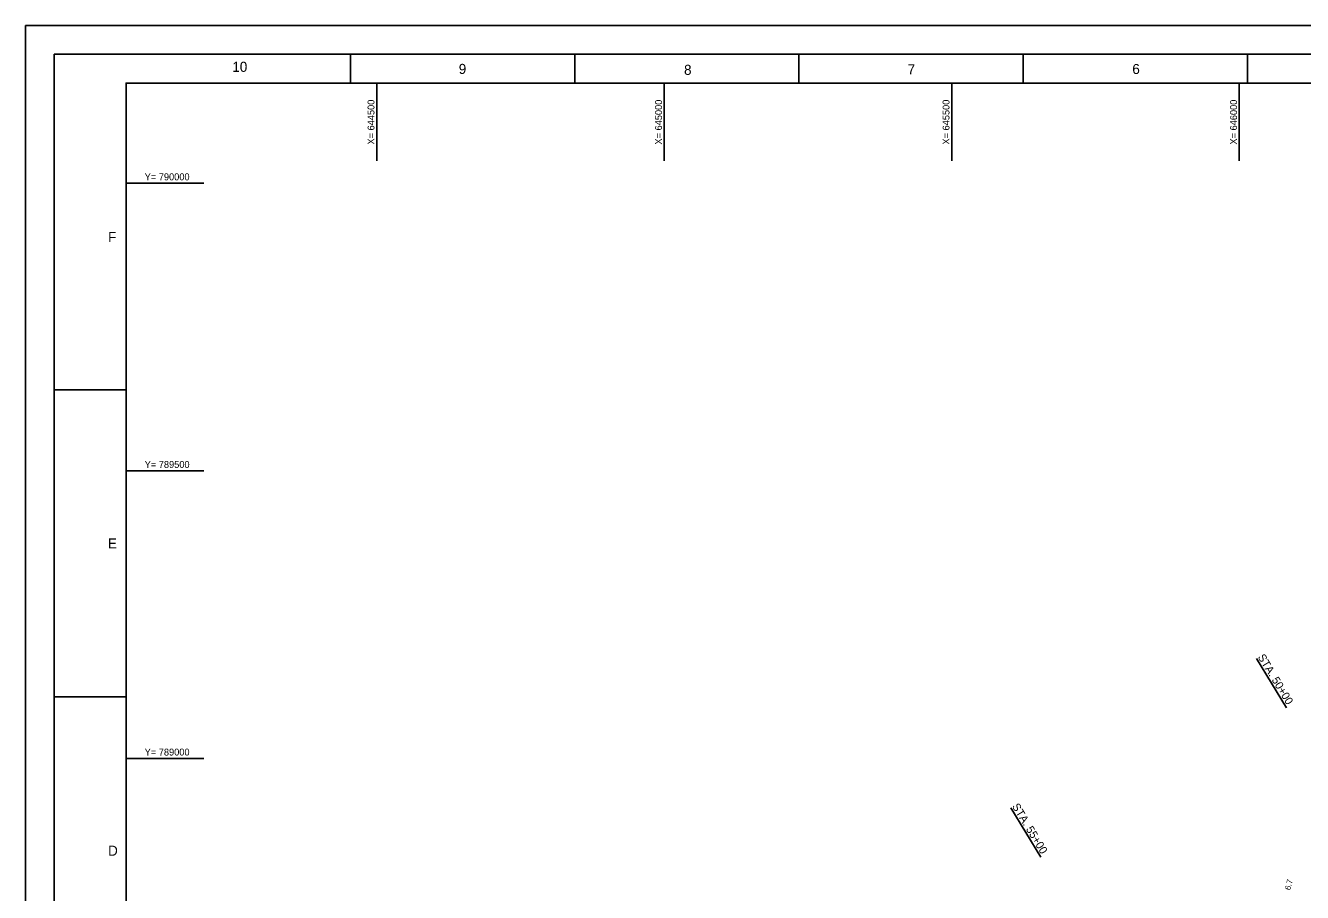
# Model space of a CAD drawing. Extents: x 643889 to 648289, y 786874 to 790274.
# Drawn here: x 643889 to 646110, y 788767 to 790274 of the extents above; entities that cross this region are included whole.
import ezdxf

# ---------------------------------------------------------------- set-up
doc = ezdxf.new("R2010")
doc.units = 0
for name, color, linetype in [('G-ANNO-NPLT', 7, 'Continuous'), ('G-ANNO-TTLB', 7, 'Continuous'), ('V-ALGN-TEXT', 7, 'Continuous'), ('V-TOPO-COOR-STAT', 7, 'Continuous'), ('V-TOPO-SOUN', 7, 'Continuous')]:
    doc.layers.add(name, color=color, linetype=linetype)

msp = doc.modelspace()

# ---------------------------------------------------------------- linework, layer by layer
at = {"layer": 'G-ANNO-NPLT'}
msp.add_lwpolyline([(643889.2, 790274), (648289.2, 790274), (648289.2, 786874), (643889.2, 786874)], close=True, dxfattribs=at)
msp.add_lwpolyline([(643889.2, 790224), (643889.2, 790274), (643939.2, 790274)], dxfattribs=at)
at = {"layer": 'G-ANNO-TTLB'}
for p, q in [((644454.2, 790224), (644454.2, 790174)), ((644844.2, 790224), (644844.2, 790174)), ((644844.2, 790224), (644844.2, 790174)), ((645234.2, 790224), (645234.2, 790174)), ((645624.2, 790224), (645624.2, 790174)), ((646014.2, 790224), (646014.2, 790174)), ((643939.2, 789640.5), (644064.2, 789640.5)), ((643939.2, 789107.2), (644064.2, 789107.2))]:
    msp.add_line(p, q, dxfattribs=at)
for points in [[(643939.2, 786924), (648239.2, 786924), (648239.2, 790224), (643939.2, 790224)], [(648189.2, 790174), (644064.2, 790174), (644064.2, 786974), (648189.2, 786974)]]:
    msp.add_lwpolyline(points, close=True, dxfattribs=at)
at = {"layer": 'V-ALGN-TEXT'}
for p, q in [((646030, 789173.4), (646081.9, 789088)), ((645602.7, 788913.9), (645654.6, 788828.4))]:
    msp.add_line(p, q, dxfattribs=at)
at = {"layer": 'V-TOPO-COOR-STAT'}
for p, q in [((644500, 790039), (644500, 790174)), ((645000, 790039), (645000, 790174)), ((645500, 790039), (645500, 790174)), ((646000, 790039), (646000, 790174)), ((644064.2, 790000), (644199.2, 790000)), ((644064.2, 789500), (644199.2, 789500)), ((644064.2, 789000), (644199.2, 789000))]:
    msp.add_line(p, q, dxfattribs=at)

# ---------------------------------------------------------------- texts
at = {"layer": 'G-ANNO-TTLB'}
for s, p in [('10', (644248.8, 790193.5)), ('9', (644642.6, 790189.9)), ('8', (645034.4, 790188.3)), ('7', (645423.1, 790189)), ('6', (645814, 790189.7)), ('F', (644032.8, 789897.6)), ('E', (644032.6, 789364.9)), ('D', (644032.8, 788830.8))]:
    msp.add_text(s, height=17.5, dxfattribs=at).set_placement(p)
at = {"layer": 'V-ALGN-TEXT'}
for s, p in [('STA. 50+00', (646031.5, 789176.3)), ('STA. 55+00', (645604.2, 788916.8))]:
    msp.add_text(s, height=13.92, rotation=301.2715, dxfattribs=at).set_placement(p)
at = {"layer": 'V-TOPO-COOR-STAT'}
for s, p in [('X= 644500', (644496, 790067.1)), ('X= 645000', (644996, 790067.1)), ('X= 645500', (645496, 790067.1)), ('X= 646000', (645996, 790067.1))]:
    msp.add_text(s, height=12, rotation=90, dxfattribs=at).set_placement(p)
for s, p in [('Y= 790000', (644096.4, 790005)), ('Y= 789500', (644096.4, 789505)), ('Y= 789000', (644096.4, 789005))]:
    msp.add_text(s, height=12, dxfattribs=at).set_placement(p)
at = {"layer": 'V-TOPO-SOUN'}
msp.add_text('6.7', height=10, rotation=76.16, dxfattribs=at).set_placement((646088.7, 788770.3))

doc.saveas('drawing.dxf')
